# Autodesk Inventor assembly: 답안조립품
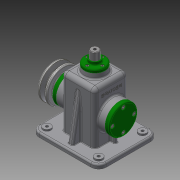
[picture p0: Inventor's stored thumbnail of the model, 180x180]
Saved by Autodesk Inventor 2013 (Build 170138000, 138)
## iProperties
Created: 2016-01
Part Number: 답안조립품
Document SubType Name: Assembly
Designer: Administrator
Author: Administrator
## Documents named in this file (19)
- C:\Users\Administrator\Desktop\460127V1003\답안조립품.iam
- C:\Users\Administrator\Desktop\460127V1003\1.본체.ipt
- C:\Users\Administrator\Desktop\460127V1003\V-벨트풀리.ipt
- C:\Users\Administrator\Desktop\460127V1003\고정핀.ipt
- C:\Users\Administrator\Desktop\460127V1003\뒤커버.ipt
- C:\Users\Administrator\Desktop\460127V1003\링크.ipt
- C:\Users\Administrator\Desktop\460127V1003\멈춤링 6 x 5.ipt
- C:\Users\Administrator\Desktop\460127V1003\멈춤링 15 x 1.ipt
- C:\Users\Administrator\Desktop\460127V1003\베어링 15 x 35 x 11.ipt
- C:\Users\Administrator\Desktop\460127V1003\볼트 M3 x 8.ipt
- C:\Users\Administrator\Desktop\460127V1003\볼트 M4 x 10.ipt
- C:\Users\Administrator\Desktop\460127V1003\볼트 M6 x 12.ipt
- C:\Users\Administrator\Desktop\460127V1003\상부부시.ipt
- C:\Users\Administrator\Desktop\460127V1003\슬라이드바.ipt
- C:\Users\Administrator\Desktop\460127V1003\앞커버.ipt
- C:\Users\Administrator\Desktop\460127V1003\오일실 15 25 7.ipt
- C:\Users\Administrator\Desktop\460127V1003\와셔.ipt
- C:\Users\Administrator\Desktop\460127V1003\키 5 x 5 x 14.ipt
- C:\Users\Administrator\Desktop\460127V1003\편심축.ipt
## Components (16 placed, 6 different names)
1. 1.본체:1
2. V-벨트풀리:1 — 각도:2
3. 고정핀:1
4. ISO 4018 M6 x 12:1
5. ISO 4762 M4 x 10:1
6. ISO 4762 M4 x 10:3
7. ISO 4762 M4 x 10:4
8. ISO 4762 M4 x 10:5
9. ISO 4762 M4 x 10:2
10. ISO 4762 M4 x 10:6
11. ISO 4762 M4 x 10:7
12. ISO 4762 M4 x 10:8
13. ISO 4762 M3 x 8:1
14. ISO 4762 M3 x 8:2
15. ISO 4762 M3 x 8:3
16. ISO 4762 M3 x 8:4
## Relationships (1: Angle 1)
- 각도:2 [Angle]: V-벨트풀리:1
